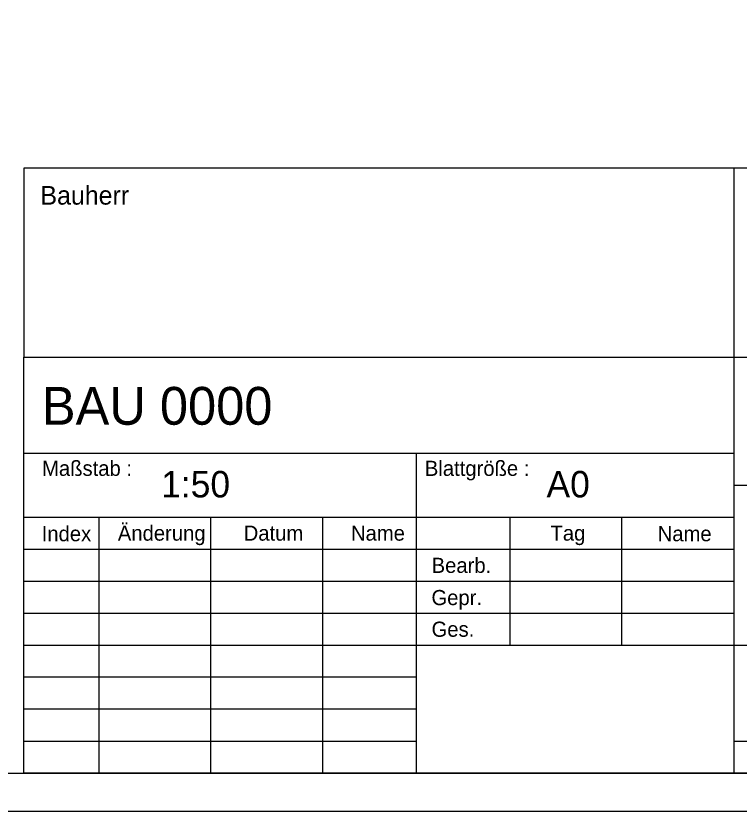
# Model space of a CAD drawing. Extents: x 0 to 59.5, y 0 to 42.1.
# Drawn here: x 50.25 to 55.03, y 0 to 5.26 of the extents above; entities that cross this region are included whole.
import ezdxf

# ---------------------------------------------------------------- set-up
doc = ezdxf.new("R2010")
doc.units = 0
doc.layers.add('90_Plankopf', color=7, linetype='Continuous')

msp = doc.modelspace()

# ---------------------------------------------------------------- linework, layer by layer
at = {"layer": '90_Plankopf'}
for p, q in [((59.2, 4.2495), (50.306, 4.2495)), ((50.306, 4.2495), (50.306, 2.9995)), ((55.0001, 2.9995), (55.0001, 4.2495)), ((50.306, 2.9995), (59.2, 2.9995)), ((50.306, 0.25), (50.306, 2.9995)), ((50.306, 2.9995), (59.2, 2.9995)), ((55.0001, 0.25), (55.0001, 2.9995)), ((50.306, 2.365), (55.0001, 2.365)), ((52.9001, 0.25), (52.9001, 2.365)), ((55.0001, 2.1535), (59.2, 2.1535)), ((50.306, 1.9435), (55.0001, 1.9435)), ((50.8001, 1.942), (50.8001, 0.25)), ((51.5413, 0.25), (51.5413, 1.942)), ((52.2825, 0.25), (52.2825, 1.942)), ((53.5177, 1.942), (53.5177, 1.096)), ((54.2589, 1.096), (54.2589, 1.942)), ((50.306, 1.7315), (55.0001, 1.7315)), ((50.306, 1.519), (55.0001, 1.519)), ((50.306, 1.3075), (55.0001, 1.3075)), ((50.306, 1.096), (55.0001, 1.096)), ((50.306, 1.096), (55.0001, 1.096)), ((52.9001, 1.096), (55.0001, 1.096)), ((55.0001, 1.096), (59.2, 1.096)), ((52.9001, 0.8845), (50.306, 0.8845)), ((52.9001, 0.673), (50.306, 0.673)), ((50.306, 0.4615), (52.9001, 0.4615)), ((55.0001, 0.4615), (59.2, 0.4615)), ((59.2, 0.25), (50.306, 0.25)), ((50.306, 0.25), (52.9001, 0.25)), ((50.89, 0.25), (59.2, 0.25)), ((50.89, 0.25), (59.2, 0.25))]:
    msp.add_line(p, q, dxfattribs=at)
for points in [[(0, 0), (59.45, 0), (59.45, 42.05), (0, 42.05)], [(1.25, 0.25), (59.2, 0.25), (59.2, 41.8), (1.25, 41.8)]]:
    msp.add_lwpolyline(points, close=True, dxfattribs=at)

# ---------------------------------------------------------------- texts
for s, height, p in [('Bauherr', 0.12318, (50.4152, 4.0088)), ('BAU 0000      ', 0.25, (50.4245, 2.5538)), ('Maßstab :', 0.1, (50.4258, 2.2158)), ('Blattgröße :', 0.099995, (52.9558, 2.2158)), ('1:50     ', 0.175, (51.2131, 2.0734)), ('A0       ', 0.175, (53.76, 2.0734)), ('Änderung', 0.1, (50.9267, 1.7875)), ('Index', 0.1, (50.4235, 1.7837)), ('Datum', 0.1, (51.7584, 1.7875)), ('Name', 0.1, (52.4674, 1.7875)), ('Tag', 0.1, (53.7862, 1.7875)), ('Name', 0.1, (54.4946, 1.7837)), ('Bearb.', 0.1, (53.0007, 1.5745)), ('Gepr.', 0.1, (52.9995, 1.3615)), ('Ges.', 0.1, (53.0002, 1.1523))]:
    msp.add_text(s, height=height, dxfattribs=at).set_placement(p)

doc.saveas('drawing.dxf')
